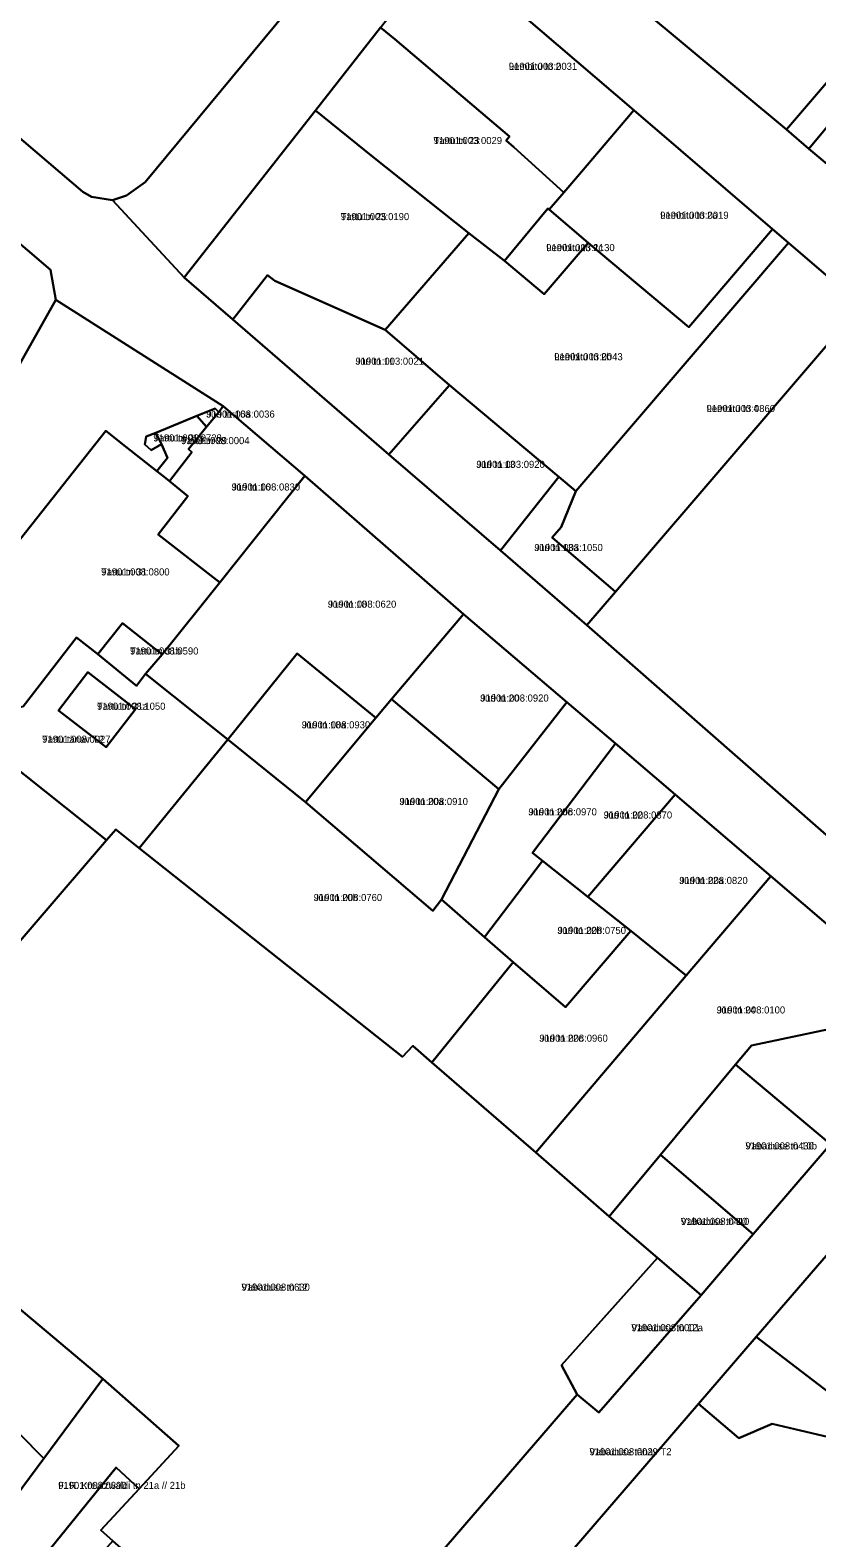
# Model space of a CAD drawing. Extents: x 675810 to 681273, y 6411190 to 6417565.
# Drawn here: x 677826.5 to 677993.2, y 6415458.6 to 6415777.9 of the extents above; entities that cross this region are included whole.
import ezdxf

# ---------------------------------------------------------------- set-up
doc = ezdxf.new("R2010")
doc.units = 0
for name, color, linetype in [('L_AADRESS', 7, 'Continuous'), ('PIIR', 7, 'Continuous'), ('TUNNUS', 7, 'Continuous')]:
    doc.layers.add(name, color=color, linetype=linetype)

msp = doc.modelspace()

# ---------------------------------------------------------------- linework, layer by layer
at = {"layer": 'PIIR'}
for points in [[(677827.43, 6415846.52), (677892.68, 6415798.34), (677892.37, 6415795.81), (677850.92, 6415745.75), (677846.94, 6415742.89), (677843.93, 6415741.95), (677839.54, 6415742.61), (677837.71, 6415743.69), (677790.48, 6415783.86), (677803.31, 6415799.07), (677793.83, 6415807.03)], [(678021.12, 6415799.06), (678011.66, 6415787.93), (678008.2, 6415772.88), (678003.37, 6415767.17), (677999.09, 6415771.21), (677986.81, 6415756.9), (677955.66, 6415782.78), (677988.86, 6415825.89)], [(677924.58, 6415808.71), (677955.66, 6415782.78), (677986.81, 6415756.9), (677991.57, 6415752.77), (678007.87, 6415739.19), (678015.33, 6415732.38), (678039.55, 6415711.57), (678068.15, 6415687.09), (678094.05, 6415664.94), (678082.36, 6415651.31), (678050.81, 6415678.36), (678032.62, 6415693.85), (678002.6, 6415719.69), (677987.22, 6415732.88), (677983.87, 6415735.76), (677954.46, 6415760.96), (677914.14, 6415795.53)], [(677914.14, 6415795.53), (677954.46, 6415760.96), (677952.98, 6415759.22), (677943.35, 6415747.91), (677939.62, 6415743.53), (677929.04, 6415753.15), (677927.37, 6415754.57), (677928.09, 6415755.41), (677903.77, 6415776.02), (677900.77, 6415778.51)], [(677900.77, 6415778.51), (677903.77, 6415776.02), (677928.09, 6415755.41), (677927.37, 6415754.57), (677929.04, 6415753.15), (677939.62, 6415743.53), (677936.54, 6415739.92), (677936.24, 6415740.16), (677927.01, 6415729.1), (677919.46, 6415734.93), (677899.13, 6415751.08), (677886.97, 6415760.95)], [(678007.87, 6415739.19), (677991.57, 6415752.77), (678008.2, 6415772.88), (678024.14, 6415759.81)], [(678003.37, 6415767.17), (677995.36, 6415757.42), (677991.57, 6415752.77), (677986.81, 6415756.9), (677999.09, 6415771.21)], [(677859.17, 6415725.55), (677886.97, 6415760.95), (677899.13, 6415751.08), (677919.46, 6415734.93), (677901.77, 6415714.45), (677878.37, 6415724.83), (677876.83, 6415726.07), (677869.45, 6415716.69)], [(677954.46, 6415760.96), (677983.87, 6415735.76), (677966.1, 6415715.01), (677944.77, 6415732.91), (677936.54, 6415739.92), (677939.62, 6415743.53), (677943.35, 6415747.91), (677952.98, 6415759.22)], [(677800.15, 6415752.64), (677801.5, 6415752.2), (677830.81, 6415727.16), (677831.96, 6415720.82), (677820.17, 6415699.87), (677800.36, 6415716.35), (677801.58, 6415717.8), (677783.74, 6415733.44)], [(677935.45, 6415722), (677927.01, 6415729.1), (677936.24, 6415740.16), (677936.54, 6415739.92), (677944.77, 6415732.91)], [(677927.01, 6415729.1), (677935.45, 6415722), (677944.77, 6415732.91), (677966.1, 6415715.01), (677983.87, 6415735.76), (677987.22, 6415732.88), (677942.18, 6415680.3), (677938.54, 6415683.35), (677915.39, 6415702.75), (677901.77, 6415714.45), (677919.46, 6415734.93)], [(678002.6, 6415719.69), (677976.46, 6415689.19), (677950.55, 6415658.97), (677937.14, 6415670.49), (677939.05, 6415672.69), (677942.18, 6415680.3), (677987.22, 6415732.88)], [(677876.83, 6415726.07), (677878.37, 6415724.83), (677901.77, 6415714.45), (677915.39, 6415702.75), (677902.53, 6415688.09), (677869.45, 6415716.69)], [(678002.6, 6415719.69), (678032.62, 6415693.85), (678017.67, 6415676.27), (678031.38, 6415664.55), (678020.32, 6415651.64), (678056.29, 6415620.89), (678026.78, 6415586.06), (678019.75, 6415586.05), (677944.51, 6415651.9), (677950.55, 6415658.97), (677976.46, 6415689.19)], [(677938.54, 6415683.35), (677926.18, 6415667.7), (677902.53, 6415688.09), (677915.39, 6415702.75)], [(677853.14, 6415692.64), (677861.84, 6415696.28), (677863.88, 6415693.94), (677860.05, 6415689.21), (677860.75, 6415688.55), (677856.04, 6415682.43), (677855.28, 6415683.03), (677853.39, 6415684.52), (677855.64, 6415687.38), (677854.38, 6415690.23)], [(677860.05, 6415689.21), (677863.88, 6415693.94), (677866.48, 6415697.06), (677867.43, 6415698.31), (677884.76, 6415683.55), (677866.72, 6415660.97), (677853.67, 6415671.09), (677859.93, 6415679.26), (677856.04, 6415682.43), (677860.75, 6415688.55)], [(677861.84, 6415696.28), (677865.7, 6415697.81), (677866.48, 6415697.06), (677863.88, 6415693.94)], [(677802.86, 6415642.95), (677842.56, 6415693.1), (677846.73, 6415689.74), (677853.39, 6415684.52), (677855.28, 6415683.03), (677856.04, 6415682.43), (677859.93, 6415679.26), (677853.67, 6415671.09), (677866.72, 6415660.97), (677854.5, 6415645.69), (677846.09, 6415652.35), (677840.84, 6415645.75), (677836.36, 6415649.29), (677825, 6415634.7), (677816.95, 6415631.79)], [(677854.38, 6415690.23), (677852.19, 6415688.97), (677850.85, 6415690.17), (677851.11, 6415691.85), (677853.14, 6415692.64)], [(677884.76, 6415683.55), (677918.32, 6415654.28), (677903.08, 6415636.23), (677899.75, 6415632.28), (677883.08, 6415645.92), (677868.41, 6415627.7), (677850.97, 6415641.61), (677854.5, 6415645.69), (677866.72, 6415660.97)], [(677942.18, 6415680.3), (677939.05, 6415672.69), (677937.14, 6415670.49), (677950.55, 6415658.97), (677944.51, 6415651.9), (677926.18, 6415667.7), (677938.54, 6415683.35)], [(677925.81, 6415617.2), (677903.08, 6415636.23), (677918.32, 6415654.28), (677940.26, 6415635.63)], [(677840.84, 6415645.75), (677846.09, 6415652.35), (677854.5, 6415645.69), (677850.97, 6415641.61), (677849.02, 6415639.07)], [(677795.01, 6415644.29), (677842.69, 6415606.39), (677812.82, 6415571.64), (677791.68, 6415590.18), (677780.97, 6415599.5), (677799.32, 6415622.46), (677786.34, 6415633.16)], [(677868.41, 6415627.7), (677883.08, 6415645.92), (677899.75, 6415632.28), (677884.84, 6415614.42)], [(677832.54, 6415633.85), (677838.75, 6415641.95), (677848.83, 6415634.16), (677842.6, 6415626.06)], [(677838.75, 6415641.95), (677832.54, 6415633.85), (677842.6, 6415626.06), (677848.83, 6415634.16)], [(677899.75, 6415632.28), (677903.08, 6415636.23), (677925.81, 6415617.2), (677913.67, 6415593.82), (677911.84, 6415591.45), (677884.84, 6415614.42)], [(677925.81, 6415617.2), (677940.26, 6415635.63), (677950.54, 6415626.89), (677932.95, 6415603.73), (677935.13, 6415602.01), (677922.83, 6415585.88), (677913.67, 6415593.82)], [(677884.84, 6415614.42), (677911.84, 6415591.45), (677913.67, 6415593.82), (677922.83, 6415585.88), (677928.88, 6415580.58), (677911.67, 6415559.3), (677907.63, 6415562.8), (677905.42, 6415560.52), (677849.65, 6415604.71), (677868.41, 6415627.7)], [(677944.7, 6415594.36), (677935.13, 6415602.01), (677932.95, 6415603.73), (677950.54, 6415626.89), (677963.18, 6415616.09)], [(677944.7, 6415594.36), (677963.18, 6415616.09), (677983.48, 6415598.78), (677965.56, 6415577.72), (677953.79, 6415587.17)], [(677939.15, 6415495.17), (677942.44, 6415488.99), (677885.15, 6415422.56), (677876.27, 6415430.13), (677861.05, 6415443.12), (677844.04, 6415458.03), (677841.47, 6415460.28), (677849.59, 6415469.04), (677858, 6415478.15), (677841.91, 6415492.28), (677783.11, 6415541.62), (677793.25, 6415553.63), (677795.68, 6415551.77), (677812.82, 6415571.64), (677842.69, 6415606.39), (677844.64, 6415608.67), (677849.65, 6415604.71), (677905.42, 6415560.52), (677907.63, 6415562.8), (677911.67, 6415559.3), (677933.66, 6415540.22), (677949.24, 6415526.71), (677959.46, 6415517.95)], [(677944.7, 6415594.36), (677953.79, 6415587.17), (677939.99, 6415571.04), (677928.88, 6415580.58), (677922.83, 6415585.88), (677935.13, 6415602.01)], [(677949.24, 6415526.71), (677933.66, 6415540.22), (677965.56, 6415577.72), (677983.48, 6415598.78), (678010.38, 6415575.72), (678003.47, 6415567.95), (677979.39, 6415562.89), (677976.02, 6415558.85), (677960.12, 6415539.77)], [(677953.79, 6415587.17), (677965.56, 6415577.72), (677933.66, 6415540.22), (677911.67, 6415559.3), (677928.88, 6415580.58), (677939.99, 6415571.04)], [(678010.38, 6415575.72), (678018.89, 6415568.59), (677996.11, 6415542.02), (677976.02, 6415558.85), (677979.39, 6415562.89), (678003.47, 6415567.95)], [(678018.89, 6415568.59), (678029.89, 6415558.54), (678006.85, 6415531.85), (677980.38, 6415501.17), (677968.13, 6415486.99), (677928.73, 6415441.3), (677913.03, 6415423.03), (677895.43, 6415402.54), (677879.19, 6415383.64), (677867.67, 6415393.29), (677889.64, 6415418.81), (677885.15, 6415422.56), (677942.44, 6415488.99), (677947.03, 6415485.15), (677968.7, 6415510.02), (677979.77, 6415522.93), (677996.11, 6415542.02)], [(677996.11, 6415542.02), (677979.77, 6415522.93), (677960.12, 6415539.77), (677976.02, 6415558.85)], [(677783.11, 6415541.62), (677841.91, 6415492.28), (677829.39, 6415475.44), (677818.94, 6415485.93), (677809.63, 6415475.43), (677800.8, 6415473.32), (677790.72, 6415479.82), (677779.68, 6415468.8), (677741.16, 6415501.73), (677778.77, 6415545.33)], [(677979.77, 6415522.93), (677968.7, 6415510.02), (677959.46, 6415517.95), (677949.24, 6415526.71), (677960.12, 6415539.77)], [(678017.36, 6415472.95), (677980.38, 6415501.17), (678006.85, 6415531.85), (678024.12, 6415516.64), (678017.21, 6415508.63), (678034.28, 6415492.8), (678020.19, 6415476.3)], [(677939.15, 6415495.17), (677959.46, 6415517.95), (677968.7, 6415510.02), (677947.03, 6415485.15), (677942.44, 6415488.99)], [(678030.59, 6415467.34), (678023.7, 6415459.23), (678000.6, 6415478.81), (677983.79, 6415482.8), (677976.68, 6415479.77), (677968.13, 6415486.99), (677980.38, 6415501.17), (678017.36, 6415472.95), (678020.19, 6415476.3)], [(677849.59, 6415469.04), (677844.71, 6415473.53), (677825.64, 6415450.04), (677815.63, 6415452.36), (677808.38, 6415444), (677806.89, 6415445.16), (677829.39, 6415475.44), (677841.91, 6415492.28), (677858, 6415478.15)], [(677806.89, 6415445.16), (677779.68, 6415468.8), (677790.72, 6415479.82), (677800.8, 6415473.32), (677809.63, 6415475.43), (677818.94, 6415485.93), (677829.39, 6415475.44)], [(677968.13, 6415486.99), (677976.68, 6415479.77), (677983.79, 6415482.8), (678000.6, 6415478.81), (678023.7, 6415459.23), (678029.87, 6415453.73), (678024.65, 6415447.54), (678032.24, 6415441.38), (678011.23, 6415415.93), (678018.43, 6415409.23), (677966.75, 6415350.05), (677934.44, 6415377.93), (677947.73, 6415393.51), (677948.93, 6415392.45), (677964.97, 6415411.06), (677928.73, 6415441.3)], [(677849.59, 6415469.04), (677841.47, 6415460.28), (677844.04, 6415458.03), (677838.9, 6415452.24), (677821.56, 6415432.66), (677808.38, 6415444), (677815.63, 6415452.36), (677825.64, 6415450.04), (677844.71, 6415473.53)]]:
    msp.add_lwpolyline(points, close=True, dxfattribs=at)
for points in [[(677900.77, 6415778.51), (677886.97, 6415760.95), (677859.17, 6415725.55), (677843.93, 6415741.95), (677846.94, 6415742.89), (677850.92, 6415745.75), (677892.37, 6415795.81)], [(677790.48, 6415783.86), (677837.71, 6415743.69), (677839.54, 6415742.61), (677843.93, 6415741.95), (677859.17, 6415725.55), (677869.45, 6415716.69), (677902.53, 6415688.09), (677926.18, 6415667.7), (677944.51, 6415651.9), (678019.75, 6415586.05), (678039.87, 6415570.55), (678063.1, 6415550.73), (678073.77, 6415541.23), (678103.1, 6415516.1), (678107.23, 6415512.56), (678121.2, 6415500.63), (678140.71, 6415483.9), (678146.81, 6415478.68), (678162.82, 6415464.74)], [(678181.09, 6415427.91), (678151.94, 6415453.26), (678131.07, 6415471.16), (678101.64, 6415496.5), (678070.82, 6415461.05), (678066.65, 6415464.64), (678097.47, 6415500.09), (678064.7, 6415528.45), (678029.89, 6415558.54), (678018.89, 6415568.59), (678010.38, 6415575.72), (677983.48, 6415598.78), (677963.18, 6415616.09), (677950.54, 6415626.89), (677940.26, 6415635.63), (677918.32, 6415654.28), (677884.76, 6415683.55), (677867.43, 6415698.31), (677831.96, 6415720.82), (677830.81, 6415727.16), (677801.5, 6415752.2)], [(677820.17, 6415699.87), (677831.96, 6415720.82), (677867.43, 6415698.31), (677866.48, 6415697.06), (677865.7, 6415697.81), (677861.84, 6415696.28), (677853.14, 6415692.64), (677851.11, 6415691.85), (677850.85, 6415690.17), (677852.19, 6415688.97), (677854.38, 6415690.23), (677855.64, 6415687.38), (677853.39, 6415684.52), (677846.73, 6415689.74), (677842.56, 6415693.1), (677802.86, 6415642.95)], [(677825, 6415634.7), (677836.36, 6415649.29), (677840.84, 6415645.75), (677849.02, 6415639.07), (677850.97, 6415641.61), (677868.41, 6415627.7), (677849.65, 6415604.71), (677844.64, 6415608.67), (677842.69, 6415606.39), (677795.01, 6415644.29)]]:
    msp.add_lwpolyline(points, dxfattribs=at)

# ---------------------------------------------------------------- texts
at = {"layer": 'L_AADRESS'}
for s, p in [('Lembitu tn 2', (677927.95, 6415769.53)), ('Tartu tn 23', (677912.02, 6415753.81)), ('Tartu tn 25', (677892.34, 6415737.7)), ('Lembitu tn 2a', (677960.04, 6415737.99)), ('Lembitu tn 2c', (677935.89, 6415731.13)), ('Jüri tn 11', (677895.46, 6415707.08)), ('Lembitu tn 2b', (677937.59, 6415708.03)), ('Lembitu tn 4', (677969.87, 6415697.06)), ('Jüri tn 16a', (677863.84, 6415695.88)), ('Tartu tn 29a', (677852.62, 6415690.83)), ('Tartu tn 29', (677858.51, 6415690.26)), ('Jüri tn 13', (677921.08, 6415685.23)), ('Jüri tn 16', (677869.21, 6415680.44)), ('Jüri tn 13a', (677933.37, 6415667.62)), ('Tartu tn 31', (677841.56, 6415662.45)), ('Jüri tn 18', (677889.61, 6415655.62)), ('Tartu tn 31b', (677847.68, 6415645.71)), ('Tartu tn 31a', (677840.68, 6415634)), ('Jüri tn 20', (677921.9, 6415635.74)), ('Jüri tn 18a', (677884.08, 6415630.07)), ('Tartu tänav T2', (677829.05, 6415627.02)), ('Jüri tn 20a', (677904.79, 6415613.84)), ('Jüri tn 20c', (677932.11, 6415611.64)), ('Jüri tn 22', (677948.07, 6415610.97)), ('Jüri tn 22a', (677964.09, 6415597.11)), ('Jüri tn 20b', (677886.61, 6415593.5)), ('Jüri tn 22b', (677938.28, 6415586.53)), ('Jüri tn 24', (677972.02, 6415569.68)), ('Jüri tn 22c', (677934.43, 6415563.7)), ('Vabaduse tn 10b', (677978.1, 6415540.89)), ('Vabaduse tn 10', (677964.42, 6415524.9)), ('Vabaduse tn 12', (677871.29, 6415510.98)), ('Vabaduse tn 12a', (677953.93, 6415502.4)), ('Vabaduse tänav T2', (677945.04, 6415476.12)), ('F. R. Kreutzwaldi tn 21a // 21b', (677832.45, 6415468.99))]:
    msp.add_text(s, height=1.5, dxfattribs=at).set_placement(p)
at = {"layer": 'TUNNUS'}
for s, p in [('91901:003:0031', (677927.95, 6415769.53)), ('91901:003:0029', (677912.02, 6415753.81)), ('91901:003:0190', (677892.34, 6415737.7)), ('91901:003:0019', (677960.04, 6415737.99)), ('91901:003:1130', (677935.89, 6415731.13)), ('91901:003:0021', (677895.46, 6415707.08)), ('91901:003:0043', (677937.59, 6415708.03)), ('91901:003:0860', (677969.87, 6415697.06)), ('91901:008:0036', (677863.84, 6415695.88)), ('91901:001:0728', (677852.62, 6415690.83)), ('91901:008:0004', (677858.51, 6415690.26)), ('91901:003:0920', (677921.08, 6415685.23)), ('91901:008:0830', (677869.21, 6415680.44)), ('91901:003:1050', (677933.37, 6415667.62)), ('91901:008:0800', (677841.56, 6415662.45)), ('91901:008:0620', (677889.61, 6415655.62)), ('91901:008:0590', (677847.68, 6415645.71)), ('91901:008:1050', (677840.68, 6415634)), ('91901:008:0920', (677921.9, 6415635.74)), ('91901:008:0930', (677884.08, 6415630.07)), ('91901:008:0027', (677829.05, 6415627.02)), ('91901:008:0910', (677904.79, 6415613.84)), ('91901:008:0970', (677932.11, 6415611.64)), ('91901:008:0870', (677948.07, 6415610.97)), ('91901:008:0820', (677964.09, 6415597.11)), ('91901:008:0760', (677886.61, 6415593.5)), ('91901:008:0750', (677938.28, 6415586.53)), ('91901:008:0100', (677972.02, 6415569.68)), ('91901:008:0960', (677934.43, 6415563.7)), ('91901:008:0430', (677978.1, 6415540.89)), ('91901:008:0410', (677964.42, 6415524.9)), ('91901:008:0630', (677871.29, 6415510.98)), ('91901:008:0001', (677953.93, 6415502.4)), ('91901:008:0029', (677945.04, 6415476.12)), ('91901:008:0390', (677832.45, 6415468.99))]:
    msp.add_text(s, height=1.5, dxfattribs=at).set_placement(p)

doc.saveas('drawing.dxf')
